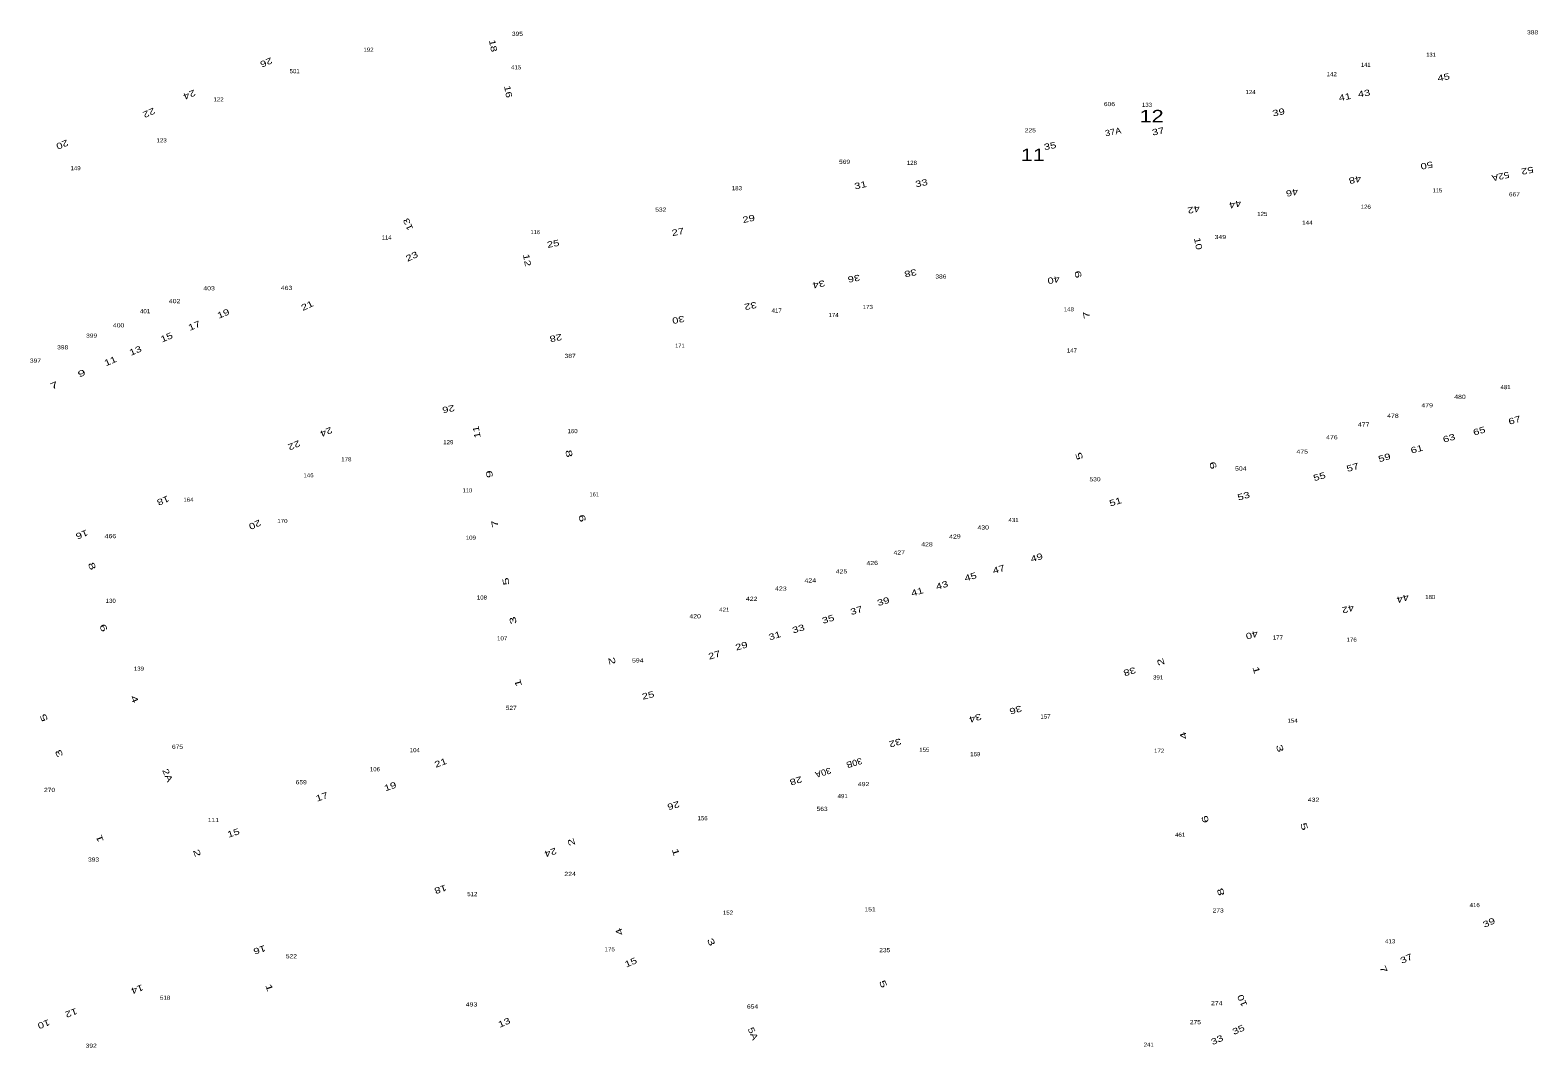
# Model space of a CAD drawing. Extents: x -828673 to -815583, y -1077737 to -1063807.
# Drawn here: x -820516.3 to -820152.3, y -1073845.3 to -1073599.5 of the extents above; entities that cross this region are included whole.
import ezdxf
from ezdxf.enums import TextEntityAlignment as Align

# ---------------------------------------------------------------- set-up
doc = ezdxf.new("R2010")
doc.units = 0
doc.header["$LTSCALE"] = 0.4
doc.layers.add('1', color=7, linetype='Continuous')
doc.layers.add('2', color=7, linetype='Continuous')

msp = doc.modelspace()

# ---------------------------------------------------------------- texts
at = {"layer": '1'}
for s, width, p in [('395', 1.2, (-820398.671, -1073600.927)), ('388', 1.2, (-820153.535, -1073600.561)), ('192', 1.1, (-820434.631, -1073604.772)), ('501', 1.1, (-820452.462, -1073609.947)), ('415', 1.1, (-820398.975, -1073609.025)), ('142', 1.1, (-820202.037, -1073610.668)), ('124', 1.1, (-820221.633, -1073614.991)), ('122', 1.1, (-820470.841, -1073616.766)), ('606', 1.2, (-820255.713, -1073617.897)), ('133', 1.1, (-820246.645, -1073618.08)), ('123', 1.1, (-820484.578, -1073626.657)), ('225', 1.2, (-820274.822, -1073624.23)), ('149', 1.1, (-820505.368, -1073633.376)), ('569', 1.2, (-820319.673, -1073631.84)), ('128', 1.1, (-820303.424, -1073632.084)), ('183', 1.1, (-820345.676, -1073638.209)), ('667', 1.2, (-820157.938, -1073639.683)), ('532', 1.2, (-820364.055, -1073643.384)), ('125', 1.1, (-820218.799, -1073644.426)), ('126', 1.1, (-820193.822, -1073642.694)), ('144', 1.15, (-820207.919, -1073646.529)), ('349', 1.25, (-820228.939, -1073649.993)), ('386', 1.2, (-820296.414, -1073659.544)), ('403', 1.25, (-820473.122, -1073662.374)), ('463', 1.25, (-820454.411, -1073662.278)), ('402', 1.25, (-820481.46, -1073665.479)), ('173', 1.1, (-820314.06, -1073666.882)), ('401', 1.1, (-820488.58, -1073667.914)), ('417', 1.1, (-820336.064, -1073667.754)), ('174', 1.1, (-820322.339, -1073668.844)), ('148', 1.1, (-820265.518, -1073667.447)), ('399', 1.2, (-820501.482, -1073673.82)), ('400', 1.25, (-820494.97, -1073671.324)), ('398', 1.2, (-820508.48, -1073676.621)), ('147', 1.1, (-820264.792, -1073677.401)), ('397', 1.2, (-820515.053, -1073679.848)), ('387', 1.2, (-820385.939, -1073678.704)), ('480', 1.25, (-820171.07, -1073688.59)), ('481', 1.1, (-820160.065, -1073686.24)), ('479', 1.25, (-820178.992, -1073690.634)), ('477', 1.25, (-820194.317, -1073695.271)), ('478', 1.25, (-820187.269, -1073693.168)), ('129', 1.1, (-820415.352, -1073699.546)), ('160', 1.1, (-820385.358, -1073696.868)), ('476', 1.25, (-820201.983, -1073698.363)), ('475', 1.25, (-820209.155, -1073701.827)), ('178', 1.1, (-820439.971, -1073703.674)), ('504', 1.25, (-820223.993, -1073705.91)), ('146', 1.1, (-820449.117, -1073707.527)), ('530', 1.2, (-820259.2, -1073708.498)), ('164', 1.1, (-820478.105, -1073713.425)), ('170', 1.1, (-820455.412, -1073718.585)), ('466', 1.25, (-820496.948, -1073722.231)), ('109', 1.1, (-820409.919, -1073722.595)), ('130', 1.1, (-820496.879, -1073737.849)), ('108', 1.1, (-820407.237, -1073737.043)), ('180', 1.1, (-820178.251, -1073736.93)), ('107', 1.1, (-820402.358, -1073746.914)), ('177', 1.1, (-820215.047, -1073746.709)), ('176', 1.1, (-820197.224, -1073747.227)), ('139', 1.1, (-820490.071, -1073754.224)), ('594', 1.25, (-820369.604, -1073752.242)), ('391', 1.1, (-820243.956, -1073756.35)), ('527', 1.2, (-820400.157, -1073763.702)), ('157', 1.1, (-820271.159, -1073765.778)), ('154', 1.1, (-820211.482, -1073766.786)), ('675', 1.2, (-820480.75, -1073773.1)), ('104', 1.1, (-820423.447, -1073773.91)), ('155', 1.1, (-820300.411, -1073773.813)), ('169', 1.1, (-820288.12, -1073774.879)), ('172', 1.1, (-820243.71, -1073774.059)), ('106', 1.1, (-820433.075, -1073778.52)), ('270', 1.2, (-820511.627, -1073783.509)), ('659', 1.2, (-820450.87, -1073781.66)), ('492', 1.25, (-820315.079, -1073782.105)), ('491', 1.1, (-820320.126, -1073785.006)), ('432', 1.25, (-820206.429, -1073785.89)), ('111', 1.2, (-820472.079, -1073790.767)), ('156', 1.1, (-820353.97, -1073790.345)), ('563', 1.2, (-820325.102, -1073788.086)), ('461', 1.1, (-820238.645, -1073794.339)), ('393', 1.2, (-820501.025, -1073800.337)), ('224', 1.25, (-820385.94, -1073803.796)), ('512', 1.1, (-820409.562, -1073808.673)), ('151', 1.2, (-820313.51, -1073812.36)), ('273', 1.2, (-820229.468, -1073812.621)), ('416', 1.1, (-820167.506, -1073811.317)), ('152', 1.1, (-820347.825, -1073813.137)), ('413', 1.1, (-820187.916, -1073820.061)), ('522', 1.2, (-820453.242, -1073823.679)), ('175', 1.1, (-820376.379, -1073821.991)), ('235', 1.2, (-820309.97, -1073822.211)), ('518', 1.1, (-820483.732, -1073833.689)), ('493', 1.25, (-820409.749, -1073835.309)), ('654', 1.2, (-820341.9, -1073835.82)), ('274', 1.25, (-820229.796, -1073835.003)), ('275', 1.2, (-820234.958, -1073839.594)), ('392', 1.2, (-820501.582, -1073845.287)), ('241', 1.1, (-820246.233, -1073845.027))]:
    msp.add_text(s, height=1, dxfattribs=dict(at, width=width)).set_placement(p, align=Align.CENTER)
for s, p in [('141', (-820193.822, -1073608.415)), ('131', (-820178.06, -1073605.979)), ('115', (-820176.511, -1073638.735)), ('116', (-820394.362, -1073648.803)), ('114', (-820430.251, -1073650.101)), ('171', (-820359.448, -1073676.255)), ('110', (-820410.744, -1073711.174)), ('161', (-820380.129, -1073712.126))]:
    msp.add_text(s, height=1, dxfattribs=at).set_placement(p, align=Align.CENTER)
for s, rotation, width, p in [('430', 1.061, 1.25, (-820286.1878, -1073720.1454)), ('431', 0.748, 1.1, (-820278.854, -1073718.3286)), ('428', 0.117, 1.25, (-820299.768, -1073724.2132)), ('429', 1.93, 1.25, (-820293.0158, -1073722.3245)), ('426', 2.33, 1.25, (-820312.9848, -1073728.7188)), ('427', 2.297, 1.25, (-820306.45, -1073726.1756)), ('425', 1.559, 1.25, (-820320.3936, -1073730.7524)), ('423', 359.072, 1.25, (-820335.0621, -1073734.8944)), ('424', 0.721, 1.25, (-820327.9448, -1073732.932)), ('421', 0.783, 1.1, (-820348.7148, -1073739.9808)), ('422', 359.258, 1.25, (-820342.106, -1073737.3649)), ('420', 0.278, 1.25, (-820355.7589, -1073741.5793))]:
    msp.add_text(s, height=1, rotation=rotation, dxfattribs=dict(at, width=width)).set_placement(p, align=Align.CENTER)
at = {"layer": '2'}
for s, rotation, width, p in [('18', 281.021, 1.35, (-820405.2654, -1073603.4476)), ('26', 202.512, 1.35, (-820459.5998, -1073606.6465)), ('45', 10.944, 1.35, (-820174.8774, -1073611.6524)), ('24', 202.901, 1.35, (-820478.1616, -1073614.4413)), ('16', 280.947, 1.35, (-820401.6153, -1073614.5276)), ('41', 11.253, 1.35, (-820198.7284, -1073616.4114)), ('43', 10.392, 1.35, (-820194.1083, -1073615.5516)), ('22', 203.736, 1.35, (-820487.9191, -1073618.8171)), ('39', 11.845, 1.35, (-820214.7159, -1073620.1062)), ('20', 202.908, 1.35, (-820508.8546, -1073626.4845)), ('37A', 11.333, 1.1, (-820254.6799, -1073624.8364)), ('37', 11.614, 1.35, (-820243.8065, -1073624.717)), ('35', 11.133, 1.35, (-820269.9148, -1073628.2515)), ('50', 191.31, 1.35, (-820179.2454, -1073631.4881)), ('52', 191.138, 1.35, (-820154.9321, -1073632.7366)), ('31', 12.052, 1.35, (-820315.6726, -1073637.6918)), ('33', 11.583, 1.35, (-820300.9516, -1073637.1998)), ('48', 191.2, 1.35, (-820196.5568, -1073634.9522)), ('52A', 192.131, 1.2, (-820161.4289, -1073634.1347)), ('46', 191.611, 1.35, (-820211.7655, -1073638.0469)), ('29', 11.871, 1.35, (-820342.6758, -1073645.8244)), ('42', 192.171, 1.35, (-820235.5064, -1073642.1314)), ('44', 191.561, 1.35, (-820225.4907, -1073640.8916)), ('13', 114.722, 1.35, (-820424.3915, -1073646.1382)), ('27', 11.338, 1.35, (-820359.7774, -1073648.9942)), ('25', 10.548, 1.35, (-820389.9018, -1073651.8596)), ('10', 282.075, 1.35, (-820235.0121, -1073651.2446)), ('23', 25.222, 1.35, (-820423.8446, -1073654.85)), ('12', 280.58, 1.35, (-820397.0657, -1073655.2193)), ('36', 190.347, 1.35, (-820317.5398, -1073658.7972)), ('38', 191.339, 1.35, (-820303.8875, -1073657.4939)), ('9', 101.389, 1.65, (-820262.553, -1073658.3786)), ('34', 191.493, 1.35, (-820326.0366, -1073660.1828)), ('40', 191.378, 1.35, (-820269.3375, -1073659.1439)), ('21', 25.327, 1.35, (-820449.1148, -1073666.7335)), ('32', 191.524, 1.35, (-820342.5227, -1073665.4146)), ('17', 22.952, 1.35, (-820476.3995, -1073671.6013)), ('19', 22.948, 1.35, (-820469.4014, -1073668.6784)), ('30', 191.261, 1.35, (-820359.9505, -1073668.7548)), ('7', 101.045, 1.65, (-820260.5165, -1073668.1867)), ('15', 22.921, 1.35, (-820483.0946, -1073674.4032)), ('28', 191.411, 1.35, (-820389.5421, -1073673.1627)), ('13', 22.952, 1.35, (-820490.6405, -1073677.6293)), ('11', 22.921, 1.35, (-820496.6746, -1073680.1492)), ('7', 22.921, 1.65, (-820510.2576, -1073686.0051)), ('9', 22.952, 1.65, (-820503.6245, -1073683.0819)), ('26', 191.653, 1.35, (-820415.476, -1073690.3119)), ('24', 203.115, 1.35, (-820445.1146, -1073695.8736)), ('11', 100.934, 1.35, (-820407.7974, -1073696.4473)), ('65', 15.832, 1.35, (-820166.2146, -1073697.0474)), ('67', 15.9, 1.35, (-820157.6825, -1073694.4478)), ('22', 202.944, 1.35, (-820452.8856, -1073699.1075)), ('63', 16.174, 1.35, (-820173.5109, -1073698.7768)), ('8', 281.117, 1.65, (-820386.9454, -1073701.9409)), ('5', 106.755, 1.65, (-820262.304, -1073702.1887)), ('59', 15.968, 1.35, (-820189.1078, -1073703.484)), ('61', 15.63, 1.35, (-820181.3031, -1073701.4328)), ('9', 100.893, 1.65, (-820404.7061, -1073706.6252)), ('6', 285.803, 1.65, (-820231.4172, -1073704.8463)), ('57', 16.174, 1.35, (-820196.7749, -1073705.8338)), ('55', 15.767, 1.35, (-820204.8118, -1073708.0612)), ('18', 202.834, 1.35, (-820484.5155, -1073712.4637)), ('51', 16.87, 1.35, (-820254.0472, -1073714.153)), ('53', 15.987, 1.35, (-820223.1116, -1073712.7615)), ('6', 281.653, 1.65, (-820383.7458, -1073717.562)), ('16', 202.024, 1.35, (-820504.1162, -1073720.6424)), ('20', 204.024, 1.35, (-820462.3437, -1073718.2883)), ('7', 101.233, 1.65, (-820403.4005, -1073718.5961)), ('8', 292.468, 1.65, (-820502.0725, -1073729.2499)), ('49', 16.887, 1.35, (-820273.0724, -1073727.6216)), ('45', 16.785, 1.35, (-820289.0486, -1073732.2721)), ('47', 16.812, 1.35, (-820282.2224, -1073730.4553)), ('5', 100.776, 1.65, (-820400.7192, -1073732.5242)), ('41', 16.768, 1.35, (-820301.9264, -1073735.8845)), ('43', 16.825, 1.35, (-820295.9486, -1073734.307)), ('37', 16.809, 1.35, (-820316.5974, -1073740.3834)), ('39', 16.754, 1.35, (-820310.1022, -1073738.2089)), ('42', 195.55, 1.35, (-820198.2919, -1073738.6134)), ('44', 195.882, 1.35, (-820185.0678, -1073736.0838)), ('3', 101.41, 1.65, (-820399.0054, -1073741.9504)), ('35', 16.861, 1.35, (-820323.425, -1073742.4892)), ('6', 293.725, 1.65, (-820499.3105, -1073744.1792)), ('31', 16.847, 1.35, (-820336.3264, -1073746.4847)), ('33', 16.723, 1.35, (-820330.6143, -1073744.8147)), ('40', 196.256, 1.35, (-820221.5185, -1073744.8873)), ('27', 16.917, 1.35, (-820350.8982, -1073751.1427)), ('29', 16.756, 1.35, (-820344.3622, -1073748.9638)), ('2', 282.94, 1.65, (-820376.5531, -1073752.0095)), ('38', 196.367, 1.35, (-820251.0432, -1073753.7283)), ('2', 106.358, 1.65, (-820242.6046, -1073751.9117)), ('1', 286.682, 1.65, (-820220.9412, -1073754.2762)), ('1', 105.767, 1.65, (-820397.8012, -1073756.9808)), ('4', 293.501, 1.65, (-820491.8032, -1073761.3879)), ('25', 13.43, 1.35, (-820366.9487, -1073760.8953)), ('36', 196.743, 1.35, (-820278.5734, -1073762.9947)), ('5', 113.215, 1.65, (-820512.3285, -1073765.2881)), ('34', 197.215, 1.35, (-820288.325, -1073764.9649)), ('32', 196.719, 1.35, (-820307.6617, -1073770.9472)), ('4', 107.361, 1.65, (-820237.1227, -1073769.7018)), ('3', 112.868, 1.65, (-820508.6601, -1073773.9305)), ('30B', 196.928, 1.1, (-820317.5491, -1073775.8015)), ('3', 287.233, 1.65, (-820215.2615, -1073773.1883)), ('2A', 293.385, 1.35, (-820483.8262, -1073779.7783)), ('21', 20.007, 1.35, (-820416.9626, -1073777.1673)), ('30A', 196.928, 1.1, (-820325.0661, -1073778.1295)), ('19', 19.667, 1.35, (-820429.1339, -1073782.8818)), ('28', 196.907, 1.35, (-820331.6289, -1073780.108)), ('17', 19.109, 1.35, (-820445.649, -1073785.384)), ('26', 196.404, 1.35, (-820361.1977, -1073786.0771)), ('6', 105.596, 1.65, (-820231.8815, -1073789.9001)), ('15', 17.958, 1.35, (-820467.0232, -1073794.1133)), ('5', 287.103, 1.65, (-820209.4045, -1073792.0629)), ('1', 109.459, 1.65, (-820498.837, -1073794.5079)), ('24', 198.476, 1.35, (-820390.8908, -1073797.4121)), ('2', 107.43, 1.65, (-820384.9467, -1073795.4032)), ('2', 289.322, 1.65, (-820476.7342, -1073798.4778)), ('1', 286.577, 1.65, (-820361.1469, -1073798.2235)), ('18', 198.398, 1.35, (-820417.4708, -1073806.3069)), ('8', 106.625, 1.65, (-820228.1189, -1073807.4446)), ('39', 23.608, 1.35, (-820163.7739, -1073815.7372)), ('4', 114.002, 1.65, (-820373.3747, -1073816.9826)), ('3', 293.215, 1.65, (-820352.5635, -1073820.0269)), ('16', 198.094, 1.35, (-820461.1521, -1073820.9363)), ('37', 24.28, 1.35, (-820183.7249, -1073824.4214)), ('15', 22.997, 1.35, (-820371.0095, -1073825.3444)), ('7', 293.496, 1.65, (-820190.2103, -1073826.628)), ('14', 200.117, 1.35, (-820490.7095, -1073830.4425)), ('1', 288.783, 1.65, (-820459.2987, -1073830.997)), ('5', 292.759, 1.65, (-820311.0248, -1073830.1679)), ('10', 113.568, 1.35, (-820222.9639, -1073833.6074)), ('12', 200.206, 1.35, (-820506.6539, -1073836.1598)), ('10', 200.746, 1.35, (-820513.2918, -1073838.8874)), ('13', 23.319, 1.35, (-820401.5689, -1073839.8782)), ('5A', 292.95, 1.3, (-820342.4709, -1073842.1676)), ('35', 23.809, 1.35, (-820224.2693, -1073841.601)), ('33', 23.775, 1.35, (-820229.4314, -1073844.061))]:
    msp.add_text(s, height=1.5, rotation=rotation, dxfattribs=dict(at, width=width)).set_placement(p, align=Align.CENTER)
at = {"layer": '2', "width": 1.3}
for s, p in [('12', (-820245.529, -1073621.8)), ('11', (-820274.219, -1073631.16))]:
    msp.add_text(s, height=3, dxfattribs=at).set_placement(p, align=Align.CENTER)

doc.saveas('drawing.dxf')
